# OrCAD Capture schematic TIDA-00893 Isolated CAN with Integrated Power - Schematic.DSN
size B
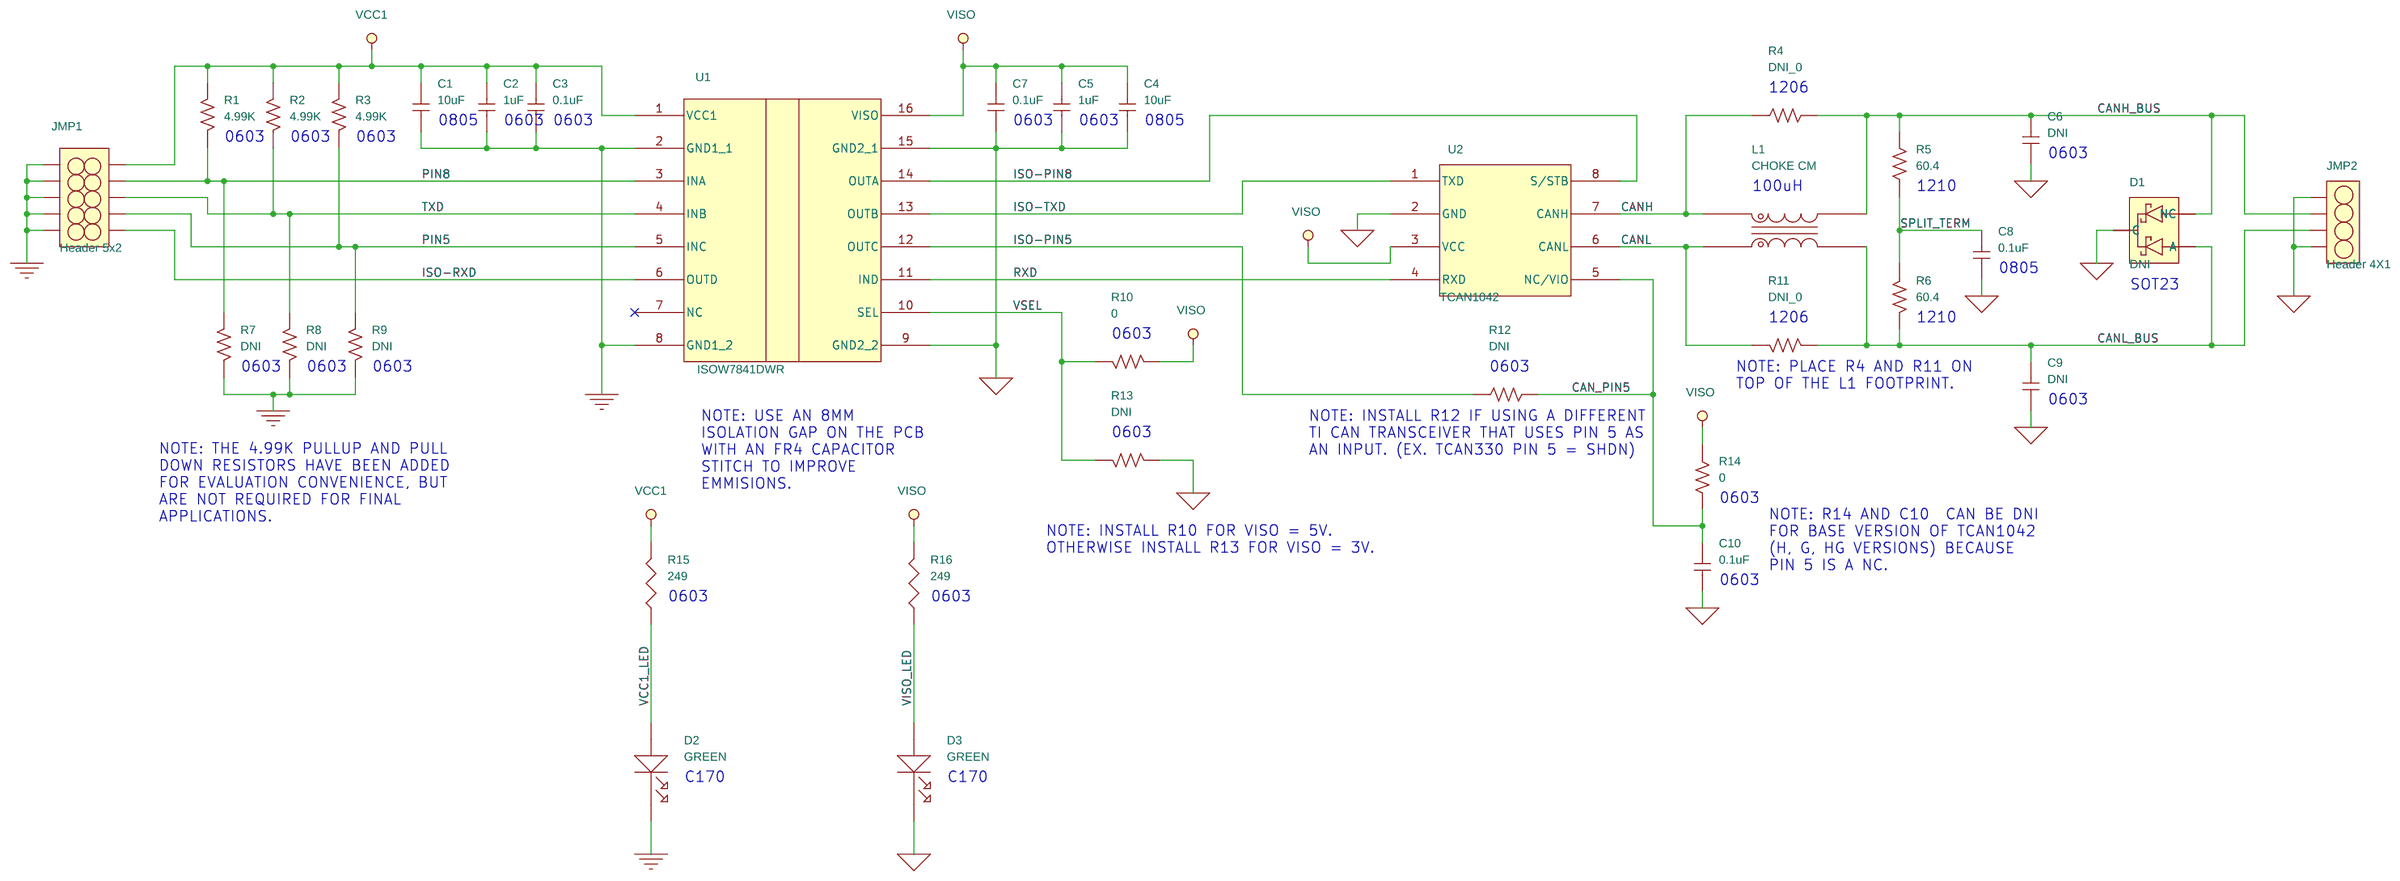
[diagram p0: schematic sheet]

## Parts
C1  10uF  [0805]
C2  1uF  [0603]
C3  0.1uF  [0603]
C4  10uF  [0805]
C5  1uF  [0603]
C6  DNI  [0603]
C7  0.1uF  [0603]
C8  0.1uF  [0805]
C9  DNI  [0603]
C10  0.1uF  [0603]
D1  DNI  [sot23]
D2  GREEN  [LED_HSMB_C170DRA]
D3  GREEN  [LED_HSMB_C170DRA]
JMP1  Header 5x2  [HDR_THVT_2X5_100]
JMP2  Header 4X1  [HDR_THVT_1X4_100]
L1  CHOKE CM  [M2022_Common-Mode_Choke]
R1  4.99K  [0603]
R2  4.99K  [0603]
R3  4.99K  [0603]
R4  DNI_0  [1206]
R5  60.4  [1210]
R6  60.4  [1210]
R7  DNI  [0603]
R8  DNI  [0603]
R9  DNI  [0603]
R10  0  [0603]
R11  DNI_0  [1206]
R12  DNI  [0603]
R13  DNI  [0603]
R14  0  [0603]
R15  249  [0603]
R16  249  [0603]
U1  ISOW7841DWR  [DW0016BHV]
U2  TCAN1042  [D8]

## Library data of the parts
C1-C10 = C
D1 = MMBD101LT1_Diode_0: Manufacturer: Semtech; Mfr_Part_Number: SM712.TCT; PART_NUMBER: MMBZ
D2 D3 = LED_HSMS: Mfr_Part_Number: HSMG-C170
JMP1 = Header_5x2
JMP2 = 4_Pin_Berg_Jumper
L1 = CHOKE_CM14
R1-R14 = R
R15 R16 = r0402
U1 = ISOW7841DWR
U2 = TCAN1042

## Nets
GND_AC: C1.2 C2.1 C3.2 D2.1 JMP1.1 JMP1.3 JMP1.5 JMP1.7 JMP1.9 R7.1 R8.1 R9.1 U1.2(GND1_1) U1.8(GND1_2)
VCC1: C1.1 C2.2 C3.1 JMP1.2 R1.2 R2.2 R3.2 R15.1 U1.1(VCC1)
VCC1_LED: D2.2 R15.2
CAN_PIN5: C10.1 R12.2 R14.2 U2.5(NC/VIO)
CANH: L1.4 R4.1 U2.7(CANH)
CANH_BUS: C6.2 D1.2(NC) JMP2.2 L1.3 R4.2 R5.2
CANL: L1.1 R11.1 U2.6(CANL)
CANL_BUS: C9.2 D1.1(A) JMP2.3 L1.2 R6.2 R11.2
ISO-PIN5: R12.1 U1.12(OUTC)
ISO-PIN8: U1.14(OUTA) U2.8(S/STB)
ISO-RXD: JMP1.10 U1.6(OUTD)
ISO-TXD: U1.13(OUTB) U2.1(TXD)
PIN5: JMP1.8 R3.1 R9.2 U1.5(INC)
PIN8: JMP1.4 R1.1 R7.2 U1.3(INA)
RXD: U1.11(IND) U2.4(RXD)
SIGNAL_GND_AC: C4.2 C5.1 C6.1 C7.1 C8.1 C9.1 C10.2 D1.3(C) D3.1 JMP2.1 JMP2.4 R13.2 U1.9(GND2_2) U1.15(GND2_1) U2.2(GND)
SPLIT_TERM: C8.2 R5.1 R6.1
TXD: JMP1.6 R2.1 R8.2 U1.4(INB)
VISO: C4.1 C5.2 C7.2 R10.2 R14.1 R16.1 U1.16(VISO) U2.3(VCC)
VISO_LED: D3.2 R16.2
VSEL: R10.1 R13.1 U1.10(SEL)

Not connected (* = marked no-connect by the designer): U1 7(NC)*

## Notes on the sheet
- 1206
- 0603
- 0603
- 0603
- 0805
- 0603
- 0603
- 0603
- 0603
- 0805
- 0603
- 100uH
- 1210
- 0805
- SOT23
- 1206
- 1210
- 0603
- 0603
- 0603
- 0603
- 0603
- NOTE: PLACE R4 AND R11 ON
  TOP OF THE L1 FOOTPRINT.
- 0603
- NOTE: USE AN 8MM
  ISOLATION GAP ON THE PCB
  WITH AN FR4 CAPACITOR
  STITCH TO IMPROVE
  EMMISIONS.
- NOTE: INSTALL R12 IF USING A DIFFERENT
  TI CAN TRANSCEIVER THAT USES PIN 5 AS
  AN INPUT. (EX. TCAN330 PIN 5 = SHDN)
- 0603
- NOTE: THE 4.99K PULLUP AND PULL
  DOWN RESISTORS HAVE BEEN ADDED
  FOR EVALUATION CONVENIENCE, BUT
  ARE NOT REQUIRED FOR FINAL
  APPLICATIONS.
- 0603
- NOTE: R14 AND C10  CAN BE DNI
  FOR BASE VERSION OF TCAN1042
  (H, G, HG VERSIONS) BECAUSE
  PIN 5 IS A NC.
- NOTE: INSTALL R10 FOR VISO = 5V.
  OTHERWISE INSTALL R13 FOR VISO = 3V.
- 0603
- 0603
- 0603
- C170
- C170
